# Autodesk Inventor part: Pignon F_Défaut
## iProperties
Shininess: 64.0
Length Units: 11269
Angle Units: 11279
Time Units: 11290
Mass Units: 11283
Length Display Precision: 3
Angle Display Precision: 2
Compacted: True
Part Number: Pignon F_Défaut
Document SubType Name: Modeling
Created: 2006-01
Material: Par défaut
Designer: Fricot
Density: 0.0
Volumn: 0.0
Area: 0.0
PropertySet Name: Model Information
Control State: 0
Master: False
Checked Out: False
Author: Fricot
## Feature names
1. Base1
